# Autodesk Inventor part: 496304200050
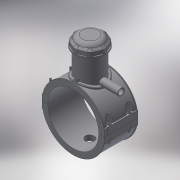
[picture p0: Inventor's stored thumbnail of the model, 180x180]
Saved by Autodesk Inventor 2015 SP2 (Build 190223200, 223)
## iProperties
Created: 2017-07
Part Number: 496304200050
Material: Generic
Description: PLASSON TAPPING SADDLE 200x50
Document SubType Name: Modeling
Designer: KIM
Mass: 1311.29 g
Surface Area: 3134.17 cm^2
Volume: 1311.29 cm^3
Density: 1 g/cm^3
Appearance: Default
Author: KIM
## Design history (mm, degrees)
derived "496304.ipt"
feature "Solid1::496304.ipt"
feature "Solid2::496304.ipt"
feature "Solid4::496304.ipt"
feature "Solid5::496304.ipt"
tag "TaggingFeature1" dims "d2" = 262.6
body "Solid1"
body "Solid2"
other parameters: "d4" = 176, "d5" = 0, "d6" = 0.1, "d8" = 0, "d19" = 6, "d20" = 6, "d21" = 105.6, "d23" = 0, "d24" = 52.8, "d26" = 0, "d29" = 3, "d30" = 66.66667, "d31" = 6, "d32" = 0, "d33" = 0, "d34" = 0.6, "d40" = 118.56, "d43" = 0, "d45" = 0, "d47" = 219.6, "d70" = 15, "d72" = 0, "d73" = 6, "d75" = 5, "d76" = 0, "d79" = 15, "d80" = 70.4, "d82" = 5 deg, "d84" = 4, "d85" = 14, "d86" = 0, "d87" = 3, "d88" = 0, "d89" = 1, "d90" = 1, "d91" = 140.8, "d92" = 0, "d93" = 0.5, "d94" = 105.26316, "d96" = 232.56, "d97" = 3.52, "d98" = 0, "d102" = 2, "d120" = 140 deg, "d121" = 24.228, "d122" = 20 deg, "d123" = 456, "d124" = 136.8, "d126" = 0, "d143" = 206, "d145" = 21.53846, "d149" = 3, "d150" = 23.69231, "d153" = 176, "d154" = 0, "d156" = 114, "d157" = 160 deg, "d159" = 5.6, "d161" = 3, "d162" = 105.6, "d163" = 0, "d168" = 111.21951, "d170" = 3, "d172" = 0, "d173" = 1, "d176" = 20 deg, "d177" = 14, "d178" = 28, "d180" = 0, "d183" = 11.2, "d184" = 11.2, "d185" = 57.2, "d186" = 57.2, "d187" = 114, "d188" = 8.4, "d189" = 14, "d190" = 0, "d191" = 171, "d193" = 5.6, "d194" = 6.16, "d195" = 90 deg, "d197" = 0, "d199" = 0, "d200" = 14, "d202" = 0, "d203" = 177, "d204" = 76, "d205" = 56, "d206" = 68, "d207" = 132.75, "d208" = 138.06, "d209" = 164.61, "d210" = 68.8, "d212" = 64, "d213" = 35.1, "d216" = 0, "d219" = 4, "d224" = 0, "d230" = 4, "d233" = 6, "d236" = 101, "d237" = 52.8, "d238" = 6.02433, "d240" = 52.8, "d241" = 52.8, "d242" = 52.8, "d243" = 6, "d244" = 52.8, "d245" = 52.8, "d246" = 52.8, "d247" = 6, "d248" = 6, "d249" = 6, "d251" = 52.8, "d253" = 6, "d254" = 6, "d255" = 52.8, "d256" = 6, "d257" = 164, "d258" = 123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
